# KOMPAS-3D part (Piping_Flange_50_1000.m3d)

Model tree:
1. Plane XY
2. Plane ZX
3. Plane ZY
4. X Axis
5. Y Axis
6. Z Axis
7. Origin
8. Sketch:1
9. Extrude:1  (labels: На расстояние 1; На расстояние 2)
     Толщина стенки 1 = 1; Толщина стенки 2 = 1; Расстояние 2 = 10
10. Offset Plane:1
11. Sketch:2
12. Sketch:3
13. Offset Plane:2
14. Sketch:4
15. Loft:2  (labels: Толщина стенки 1; Толщина стенки 2)
16. Chamfer:2
     Угол = 26.5651
17. Sketch:7
18. Cut-Extrude:2  (labels: На расстояние 1)
     Толщина стенки 1 = 1; Толщина стенки 2 = 1; Расстояние 1 = 10; Расстояние 2 = 9
19. Intersection Axis of Two Planes:1
20. Circular Pattern:1  (labels: Экземпляр ( 1, 2 );; Вырезать элемент выдавливания:2; Экземпляр ( 1, 3 );; Вырезать элемент выдавливания:2)
     N 1 = 1; Шаг 1 = 10; Шаг 2 = 360
21. Offset Plane:3
22. Sketch:8
23. Extrude:3  (labels: На расстояние 2)
     Толщина стенки 1 = 1; Толщина стенки 2 = 1; Расстояние 1 = 3; Угол 1 = 45; Расстояние 2 = 10
24. Sketch:6
25. Cut-Extrude:1  (labels: На расстояние 1; На расстояние 2)
     Толщина стенки 1 = 1; Толщина стенки 2 = 1; Расстояние 1 = 42; Расстояние 2 = 3
26. Sketch:9
27. Attachment Point:1
28. Sketch:10
29. Attachment Point:2  (labels: C:\Program Files\ASCON\KOMPAS-3D V10\Sys\graphic.lyt; Flange Dn 50; Piping_Flange_50_1000.m3d; Tank 2.a3d)

Expressions: (Dn-d1)*0.5-1; (Dm-Dn)*1.25; f*SIND(30)
Referenced files in C:\Documents and Settings\kashirsky\Мои документы\Camtasia Studio\Pipelines3D\Tanks\: Piping_Flange_50_1000.m3d, Tank 2.a3d, Tank 2.spw, Tank 1.a3d, Tank 1.spw, Tanks_step 1.a3d, Tanks_step 1.spw, Tanks_step 2.a3d, Tanks_step 3.a3d, Tanks_step 4.a3d
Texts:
  Flange Dn 50
  Steel ASTM A295
  Three Point Plane
  Plane at Angle
  Line and Point Plane
  Axis through Two Vertices
  Axis of Feature
  Axis of Conical Surface
  Axis through Edge
  Приклеить элемент выдавливания
  Приклеить элемент вращения
  Приклеить кинематический элемент
  Приклеить элемент по сечениям
  Trim by Surface
  Trim by Sketch
  Feature with No History
  Intersection Axis of Two Planes
  Two Line Plane
  Line and Face Plane
  Bend by line
  Hole in sheet body
  Cut in sheet body
  Point in CM
  Linear Dimension from Line to Point
  Surface Finish Symbol
  Geometric Tolerance Symbol
  Текст на чертеже
  Линия-выноска #1
  Линия-выноска #2
  Линия-выноска #3
  Отклонения формы и база
  Марка координационной оси
  Марка/позиционное обозначение с линией-выноской
  Марка/позиционное обозначение на линии
  Марка/позиционное обозначение без линии-выноски
  Экземпляр ( 1, 2 );
  Экземпляр ( 1, 3 );
  Экземпляр ( 1, 4 );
